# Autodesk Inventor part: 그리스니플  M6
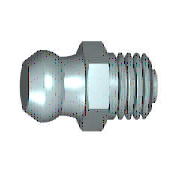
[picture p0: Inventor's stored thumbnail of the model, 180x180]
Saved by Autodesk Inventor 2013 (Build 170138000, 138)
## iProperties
IsCustomPart: 1
Created: 2012-02
Part Number: 그리스니플  M6
Material: 강철, 연강
Description: 그리스 니플에 대한 사양. 제I부: 버튼 머리 그리스 니플 유형 A
Document SubType Name: Modeling
Standard: IS 4009
Designer: mduedu
Standards Organization: IS
Language: ko-KR
Size Designation: M6 원추 짧은
Categories: <MemberInstance><Categories><Category DisplayName="기타 부품" InternalName="5aa15e00-363f-49f2-933f-16f664388e3f" Mnemonic="OTHER"><Category DisplayName="그리스 부속품" I
Density: 1 g/cm^3
Author: mduedu
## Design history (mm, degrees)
sketch "스케치1"
  geometry: L1 (-9.8, 0)-(-9.8, 2.25); L2 (-9.8, 2.25)-(-8.055, 3.194); L3 (-9.8, 0)-(6.2, 0); L4 (6.2, 0)-(6.2, 1.5); L5 (6.2, 1.5)-(5.5, 1.5); L6 (5.5, 1.5)-(5.5, 3); L7 (5.5, 3)-(0, 3); L8 (-13, 0)-(9.4, 0) reference; L9 (0, -1.725)-(0, 10.35) reference; L10 (-3, 3.5)-(0, 3.5); L11 (0, 3.5)-(0, 3); A1 r 3.25 centre (-7.455, 0) between (-5.573, 2.65) and (-8.055, 3.194); A2 r 6 centre (-6.12, 8.625) between (-5.573, 2.65) and (-3, 3.5)
  constraints: 18 end point, 5 perpendicular, 4 point on circle, 2 centre point, 2 parallel, 2 point on line, 1 collinear, 1 vertical
  dimensions: "d0" = 16 distance between parallel lines of L1 L4 (= GL); "d1" = 5.3 diameter of A1.start L3 (= KGB2); "d2" = 0.7 distance between parallel lines of L4 L6 (= PHH); "d3" = 3 diameter of L5 L3 (= 0.5 x NND); "d4" = 6 diameter of L7 L3 (= NND); "d5" = 6.5 dimension on A1 L3 (= KR); "d6" = 4.5 diameter of L1.end L3 (= KGB1); "d7" = 6 radius of A2 (= RBN); "d11" = 7 diameter of L10.start L3 (= SW); "d14" = 3 distance of L10.start L10.end (= KOH); "d15" = 5.5 distance between parallel lines of L6 L11 (= NLG); "d61" = 8.05479 distance from line of L9 L2.end (computed from KGB1, KR, PHH, GL, NLG, VERS); "d62" = 7.45479 distance from line of L9 A1.centre (computed from NLG, GL, PHH, KR, KGB1)
revolve "본체" sketch "스케치1" stored, may be unused: angle "d25" = 90 deg
sketch "스케치2"
  geometry: L1 (2.021, 3.5)-(4.041, 0); L2 (4.041, 0)-(2.021, -3.5); L3 (2.021, -3.5)-(-2.021, -3.5); L4 (-2.021, -3.5)-(-4.041, 0); L5 (-4.041, 0)-(-2.021, 3.5); L6 (-2.021, 3.5)-(2.021, 3.5); C1 r 3.5 at (0, 0) reference; 1 further point
  constraints: 12 end point, 1 coincident, 1 horizontal, 1 tangent, 11 other
extrude "머리" join sketch "스케치2" distance "d17" = 3 (= KOH); taper "d18" = 0 deg
sketch "스케치3"
  geometry: L1 (2.687, 4.041)-(3, 4.041); L2 (3, 4.041)-(3, 3.5); L3 (3, 3.5)-(2.687, 4.041); L4 (0.313, 4.041)-(0, 4.041); L5 (0, 4.041)-(0, 3.5); L6 (0, 3.5)-(0.313, 4.041); L7 (3.6, 0)-(-0.6, 0) reference; L8 (0, 4.041)-(0, 2.021) reference; L9 (0, 4.041)-(3, 4.041) reference; L10 (3, 3.031)-(3, 4.041) reference
  constraints: 12 end point, 4 collinear, 3 perpendicular, 1 horizontal
  dimensions: "d19" = 3.5 distance from line of L5.end L7 (= 0.5 x SW); "d20" = 3.5 distance from line of L2.end L7 (= 0.5 x SW); "d21" = 30 deg angle of L6 L5; "d22" = 30 deg angle of L2 L3
revolve "모따기1" sketch "스케치3" stored, may be unused: angle "d56" = 90 deg
body "Solid1"
fillet "모깎기1" dims "d8" = 0.2 (= RR)
feature "스레드1" dims "d9" = 4.88655 (= NLG - GAL), "d10" = 0
chamfer "모따기2" distance "d23" = 0.61345 (= -0.5 x GD1 + 0.5 x NND); stored, may be unused: angle "d24" = 45 deg, second distance "d59" = 0.61345 (= -0.5 x GD1 + 0.5 x NND)
other parameters: "NLG" = 5.5 [user parameter; used in 4 equation terms], "GL" = 16 [user parameter; used in 3 equation terms], "NND" = 6 [user parameter; used in 4 equation terms], "KGB1" = 4.5 [user parameter; used in 3 equation terms], "KGB2" = 5.3 [user parameter; used in 1 equation term], "VERS" = 0.6 [user parameter; used in 1 equation term], "KR" = 6.5 [user parameter; used in 3 equation terms], "RBN" = 6 [user parameter; used in 1 equation term], "SW" = 7 [user parameter; used in 3 equation terms], "KOH" = 3 [user parameter; used in 2 equation terms], "GAL" = 0.61345 (= 0.61345 x PTC) [user parameter; used in 1 equation term], "FAWI" = 45 deg [user parameter], "PHH" = 0.7 [user parameter; used in 3 equation terms], "GD1" = 4.7731 (= THREADDIA - 1.2269 x PTC) [user parameter; used in 2 equation terms], "RR" = 0.2 [user parameter; used in 1 equation term], "d12" = 0, "d13" = 0, "GUL" = 0.61345 (= 0.61345 x PTC) [user parameter], "DULO" = 1.5 [user parameter], "PTC" = 1 [user parameter; used in 4 equation terms], "GEL" = 5.5 [user parameter], "THREADDIA" = 6 [user parameter; used in 1 equation term], "TOA" = 30 deg [user parameter]
